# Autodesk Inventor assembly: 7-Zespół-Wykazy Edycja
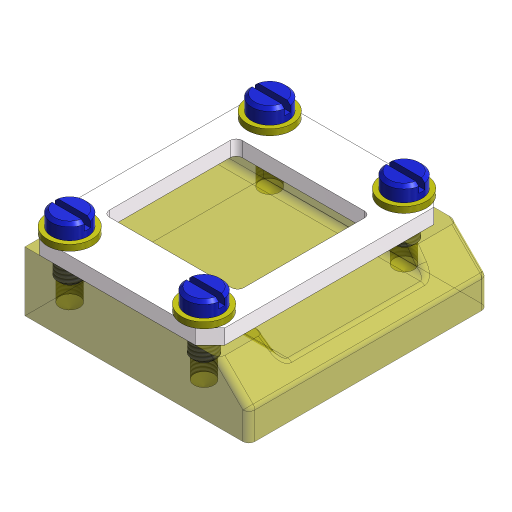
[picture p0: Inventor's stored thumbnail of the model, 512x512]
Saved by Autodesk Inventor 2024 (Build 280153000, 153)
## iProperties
Company: ATC
Shininess: 20.0
Length Units: 11269
Angle Units: 11279
Time Units: 11290
Mass Units: 11283
Length Display Precision: 3
Angle Display Precision: 2
Compacted: True
Created: 2023-03
Part Number: 7-Zespół-Wykazy Edycja
Document SubType Name: Assembly
Designer: Andrzej Jaskulski
Stock Number: 7-Zespół-Wykazy Edycja
Checked By: A.J.
Engr Approved By: Andrzej Jaskulski
Mfg Approved By: Andrzej Jaskulski
Authority: A.J.
Density: 0.0
Volumn: 0.0
Area: 0.0
PropertySet Name: Model Information
Control State: 0
Master: False
Checked Out: False
Title: A.J.: Kurs R2024-MEP
Author: Andrzej Jaskulski
Revision Number: 1/24
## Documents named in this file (3)
- C:\Users\AndJas\Documents\R2024-MEP\Obszar roboczy\7-Zespół-Wykazy Edycja.iam
- C:\Users\AndJas\Documents\R2024-MEP\Obszar roboczy\P.ipt
- C:\Users\AndJas\Documents\R2024-MEP\Obszar roboczy\Mocowanie-E.iam
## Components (2 placed, 2 different names)
1. Płyta — Wstaw:1, Wstaw:2
2. Mocowanie-E:1 [sub-assembly] — Wstaw:1, Wstaw:2
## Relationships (2: Insert 2)
- Wstaw:1 [Insert]: Płyta ↔ Mocowanie-E:1
- Wstaw:2 [Insert]: Płyta ↔ Mocowanie-E:1
